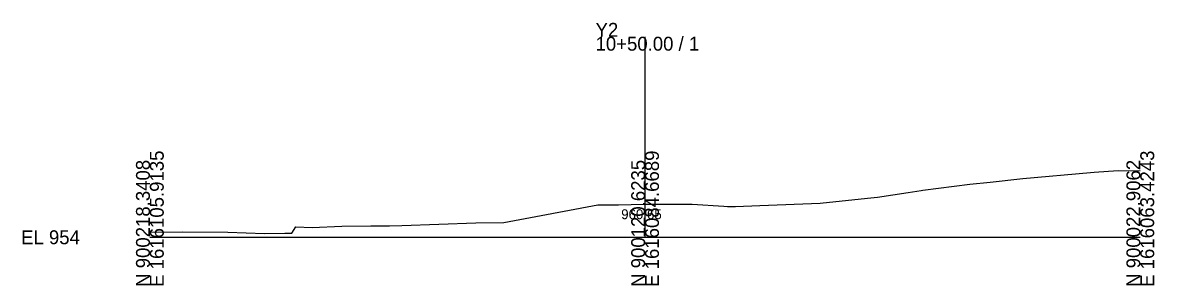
# Model space of a CAD drawing. Extents: x -26 to 1403, y -10 to 2517.
# Drawn here: x -25.7 to 202.8, y 490.3 to 543.3 of the extents above; entities that cross this region are included whole.
import ezdxf

# ---------------------------------------------------------------- set-up
doc = ezdxf.new("R2010")
doc.units = 0
for name, color, linetype in [('Exist Cross Section Cell', 7, 'Continuous'), ('Exist XS Center Line Elevation Label', 7, 'Continuous'), ('Exist XS Ground Line', 7, 'Continuous')]:
    doc.layers.add(name, color=color, linetype=linetype)

msp = doc.modelspace()

# ---------------------------------------------------------------- linework, layer by layer
at = {"layer": 'Exist Cross Section Cell'}
for p, q in [((100, 500), (100, 540.43)), ((0, 500), (100, 500)), ((100, 500), (200, 500))]:
    msp.add_line(p, q, dxfattribs=at)
at = {"layer": 'Exist XS Ground Line'}
for p, q in [((176.29, 511.87), (189.96, 513.08)), ((189.96, 513.08), (190.7, 513.14)), ((190.7, 513.14), (195.5, 513.45)), ((195.5, 513.45), (199.32, 513.39)), ((199.32, 513.39), (200, 513.48)), ((156.06, 509.47), (165.61, 510.68)), ((165.61, 510.68), (169.65, 511.12)), ((169.65, 511.12), (176.29, 511.87)), ((138.53, 507.23), (145.59, 507.94)), ((145.59, 507.94), (146.93, 508.12)), ((146.93, 508.12), (153.11, 509.06)), ((153.11, 509.06), (155.73, 509.44)), ((155.73, 509.44), (156.06, 509.47)), ((77.92, 504.17), (90.45, 506.51)), ((90.45, 506.51), (94.66, 506.56)), ((94.66, 506.56), (99.78, 506.65)), ((99.78, 506.65), (103.5, 506.66)), ((103.5, 506.66), (109.53, 506.66)), ((109.53, 506.66), (115.91, 506.25)), ((115.91, 506.25), (116.64, 506.23)), ((116.64, 506.23), (118.28, 506.2)), ((118.28, 506.2), (123.15, 506.38)), ((123.15, 506.38), (135.35, 506.89)), ((135.35, 506.89), (138.53, 507.23)), ((50.91, 502.35), (65.85, 502.93)), ((65.85, 502.93), (71.5, 502.99)), ((71.5, 502.99), (77.92, 504.17)), ((0, 501.05), (6.58, 501.08)), ((6.58, 501.08), (15.72, 501.04)), ((15.72, 501.04), (23.17, 500.77)), ((23.17, 500.77), (27.22, 500.8)), ((27.22, 500.8), (28.69, 500.81)), ((28.69, 500.81), (29.47, 502.08)), ((29.47, 502.08), (32.74, 501.98)), ((32.74, 501.98), (38.78, 502.26)), ((38.78, 502.26), (44.63, 502.31)), ((44.63, 502.31), (48.38, 502.33)), ((48.38, 502.33), (50.91, 502.35))]:
    msp.add_line(p, q, dxfattribs=at)

# ---------------------------------------------------------------- texts
at = {"layer": 'Exist Cross Section Cell'}
for s, p in [('Y2', (90, 540.43)), ('10+50.00 / 1', (90, 537.63)), ('EL 954', (-26, 498.6))]:
    msp.add_text(s, height=2.8, dxfattribs=at).set_placement(p)
for s, p in [('E 1616105.9135', (2.8, 490)), ('E 1616084.6689', (102.8, 490)), ('E 1616063.4243', (202.8, 490)), ('N 900218.3408', (0, 490)), ('N 900120.6235', (100, 490)), ('N 900022.9062', (200, 490))]:
    msp.add_text(s, height=2.8, rotation=90, dxfattribs=at).set_placement(p)
at = {"layer": 'Exist XS Center Line Elevation Label'}
msp.add_text('960.65', height=2, dxfattribs=at).set_placement((95.18, 503.65))

doc.saveas('drawing.dxf')
